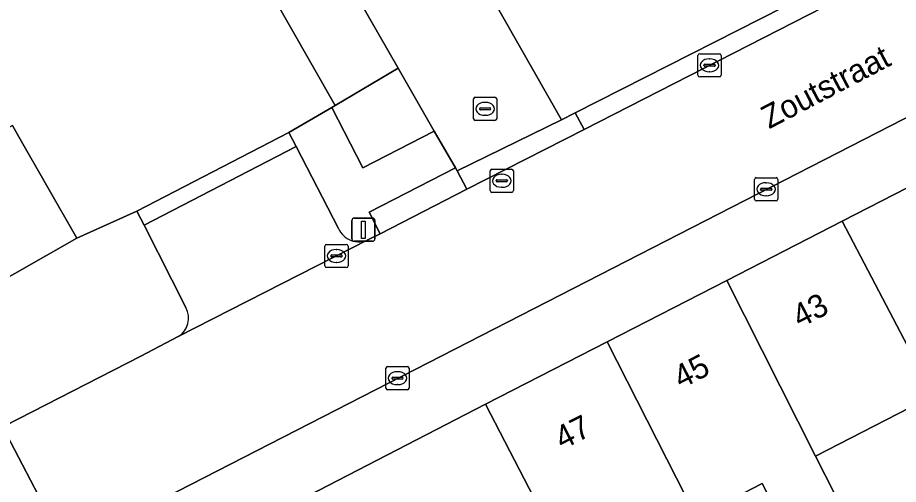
# Model space of a CAD drawing. Extents: x 159888 to 160761, y 384031 to 384750.
# Drawn here: x 160531.08 to 160569.11, y 384284.4 to 384304.54 of the extents above; entities that cross this region are included whole.
import ezdxf

# ---------------------------------------------------------------- set-up
doc = ezdxf.new("R2010")
doc.units = 0
for name, color, linetype in [('IMGEO_Erf', 7, 'Continuous'), ('IMGEO_Groenvoorziening', 7, 'Continuous'), ('IMGEO_Kolk', 7, 'Continuous'), ('IMGEO_Lichtmast', 7, 'Continuous'), ('IMGEO_Openbare_ruimte_label', 7, 'Continuous'), ('IMGEO_Pand', 7, 'Continuous'), ('IMGEO_Pand_nummerreeks', 7, 'Continuous'), ('IMGEO_Parkeervlak_open', 7, 'Continuous'), ('IMGEO_Rijbaan_lokaal_open', 7, 'Continuous'), ('IMGEO_Rioolput', 7, 'Continuous'), ('IMGEO_Voetpad_open', 7, 'Continuous')]:
    doc.layers.add(name, color=color, linetype=linetype)

msp = doc.modelspace()

# ---------------------------------------------------------------- linework, layer by layer
at = {"layer": 'IMGEO_Erf'}
for points in [[(160530.86, 384299.884), (160531.135, 384299.401), (160533.646, 384295.03), (160536.236, 384296.185), (160542.794, 384299.585), (160544.644, 384300.668), (160544.79, 384300.753), (160541.82, 384305.981), (160540.039, 384305.037), (160538.682, 384307.598), (160541.063, 384308.86), (160543.1, 384310.052), (160531.789, 384330.089), (160529.359, 384328.855)], [(160570.633, 384288.242), (160565.536, 384285.62), (160566.384, 384283.945), (160564.075, 384282.776), (160563.235, 384284.436), (160560.401, 384282.978), (160555.203, 384280.304), (160559.938, 384270.993), (160560.964, 384268.976), (160556.833, 384267.08), (160556.642, 384267.456), (160556.135, 384267.254), (160556.26, 384266.871), (160551.702, 384264.96), (160543.477, 384260.72), (160543.642, 384260.525), (160565.32, 384270.954), (160568.138, 384265.216), (160563.733, 384263.06), (160566.28, 384257.873)]]:
    msp.add_lwpolyline(points, dxfattribs=at)
at = {"layer": 'IMGEO_Groenvoorziening'}
msp.add_lwpolyline([(160558.102, 384270.191), (160559.938, 384270.993), (160555.203, 384280.304), (160553.584, 384283.42), (160551.279, 384287.856), (160533.88, 384278.879), (160536.442, 384278.002), (160537.944, 384277.697), (160549.322, 384283.817), (160551.212, 384280.795), (160550.654, 384280.266), (160550.225, 384279.629), (160550.169, 384278.862), (160550.319, 384278.053), (160551.037, 384276.806), (160552.885, 384276.185), (160550.436, 384268.6), (160548.359, 384269.253), (160543.871, 384263.833), (160544.188, 384263.332), (160544.342, 384263.416), (160550.681, 384266.684), (160553.787, 384268.003), (160553.651, 384268.417)], close=True, dxfattribs=at)
at = {"layer": 'IMGEO_Kolk'}
for p, q in [((160560.532, 384302.984), (160561.384, 384302.984)), ((160560.457, 384302.058), (160560.457, 384302.91)), ((160560.945, 384302.764), (160560.97, 384302.764)), ((160561.458, 384302.91), (160561.458, 384302.058)), ((160560.716, 384302.478), (160560.716, 384302.49)), ((160561.154, 384302.441), (160560.756, 384302.441)), ((160560.759, 384302.527), (160561.157, 384302.527)), ((160561.2, 384302.49), (160561.2, 384302.478)), ((160561.384, 384301.984), (160560.532, 384301.984)), ((160560.968, 384302.204), (160560.943, 384302.204)), ((160550.842, 384301.106), (160551.694, 384301.106)), ((160550.767, 384300.18), (160550.767, 384301.032)), ((160551.255, 384300.886), (160551.28, 384300.886)), ((160551.768, 384301.032), (160551.768, 384300.18)), ((160551.026, 384300.6), (160551.026, 384300.612)), ((160551.464, 384300.563), (160551.066, 384300.563)), ((160551.069, 384300.649), (160551.467, 384300.649)), ((160551.278, 384300.326), (160551.253, 384300.326)), ((160551.51, 384300.612), (160551.51, 384300.6)), ((160551.694, 384300.106), (160550.842, 384300.106)), ((160562.901, 384296.709), (160562.901, 384297.561)), ((160562.976, 384297.635), (160563.828, 384297.635)), ((160563.389, 384297.415), (160563.414, 384297.415)), ((160563.902, 384297.561), (160563.902, 384296.709)), ((160563.16, 384297.129), (160563.16, 384297.141)), ((160563.598, 384297.092), (160563.2, 384297.092)), ((160563.203, 384297.178), (160563.601, 384297.178)), ((160563.644, 384297.141), (160563.644, 384297.129)), ((160563.828, 384296.635), (160562.976, 384296.635)), ((160563.412, 384296.855), (160563.387, 384296.855)), ((160544.349, 384293.831), (160544.349, 384294.683)), ((160544.424, 384294.757), (160545.276, 384294.757)), ((160545.35, 384294.683), (160545.35, 384293.831)), ((160544.608, 384294.251), (160544.608, 384294.263)), ((160544.651, 384294.3), (160545.049, 384294.3)), ((160544.837, 384294.537), (160544.862, 384294.537)), ((160545.092, 384294.263), (160545.092, 384294.251)), ((160545.046, 384294.214), (160544.648, 384294.214)), ((160544.86, 384293.977), (160544.835, 384293.977)), ((160545.276, 384293.757), (160544.424, 384293.757)), ((160546.984, 384288.558), (160546.984, 384289.41)), ((160547.059, 384289.484), (160547.911, 384289.484)), ((160547.985, 384289.41), (160547.985, 384288.558)), ((160547.243, 384288.978), (160547.243, 384288.99)), ((160547.681, 384288.941), (160547.283, 384288.941)), ((160547.286, 384289.027), (160547.684, 384289.027)), ((160547.472, 384289.264), (160547.497, 384289.264)), ((160547.727, 384288.99), (160547.727, 384288.978)), ((160547.495, 384288.704), (160547.47, 384288.704)), ((160547.911, 384288.484), (160547.059, 384288.484))]:
    msp.add_line(p, q, dxfattribs=at)
for points in [[(160560.532, 384302.984), (160561.384, 384302.984)], [(160560.457, 384302.058), (160560.457, 384302.91)], [(160561.458, 384302.91), (160561.458, 384302.058)], [(160561.384, 384301.984), (160560.532, 384301.984)], [(160550.842, 384301.106), (160551.694, 384301.106)], [(160550.767, 384300.18), (160550.767, 384301.032)], [(160551.768, 384301.032), (160551.768, 384300.18)], [(160551.694, 384300.106), (160550.842, 384300.106)], [(160562.901, 384296.709), (160562.901, 384297.561)], [(160562.976, 384297.635), (160563.828, 384297.635)], [(160563.902, 384297.561), (160563.902, 384296.709)], [(160563.828, 384296.635), (160562.976, 384296.635)], [(160544.349, 384293.831), (160544.349, 384294.683)], [(160544.424, 384294.757), (160545.276, 384294.757)], [(160545.35, 384294.683), (160545.35, 384293.831)], [(160545.276, 384293.757), (160544.424, 384293.757)], [(160546.984, 384288.558), (160546.984, 384289.41)], [(160547.059, 384289.484), (160547.911, 384289.484)], [(160547.985, 384289.41), (160547.985, 384288.558)], [(160547.911, 384288.484), (160547.059, 384288.484)]]:
    msp.add_lwpolyline(points, dxfattribs=at)
for centre, radius, start, end in [((160560.534, 384302.908), 0.0765, 91.552, 178.448), ((160560.534, 384302.908), 0.0765, 91.552, 178.448), ((160561.382, 384302.908), 0.0765, 1.552, 88.448), ((160561.382, 384302.908), 0.0765, 1.552, 88.448), ((160560.756, 384302.487), 0.0403, 85.8775, 175.7526), ((160560.753, 384302.477), 0.0366, 178.938, 274.7102), ((160561.157, 384302.484), 0.043, 264.8664, 352.4533), ((160561.161, 384302.489), 0.0386, 1.7309, 96.639), ((160560.534, 384302.06), 0.0765, 181.552, 268.448), ((160560.534, 384302.06), 0.0765, 181.552, 268.448), ((160561.382, 384302.06), 0.0765, 271.552, 358.448), ((160561.382, 384302.06), 0.0765, 271.552, 358.448), ((160550.844, 384301.03), 0.0765, 91.552, 178.448), ((160550.844, 384301.03), 0.0765, 91.552, 178.448), ((160551.692, 384301.03), 0.0765, 1.552, 88.448), ((160551.692, 384301.03), 0.0765, 1.552, 88.448), ((160551.066, 384300.609), 0.0403, 85.8775, 175.7526), ((160551.063, 384300.599), 0.0366, 178.938, 274.7102), ((160551.467, 384300.606), 0.043, 264.8664, 352.4533), ((160551.471, 384300.611), 0.0386, 1.7309, 96.639), ((160550.844, 384300.182), 0.0765, 181.552, 268.448), ((160550.844, 384300.182), 0.0765, 181.552, 268.448), ((160551.692, 384300.182), 0.0765, 271.552, 358.448), ((160551.692, 384300.182), 0.0765, 271.552, 358.448), ((160562.978, 384297.559), 0.0765, 91.552, 178.448), ((160562.978, 384297.559), 0.0765, 91.552, 178.448), ((160563.826, 384297.559), 0.0765, 1.552, 88.448), ((160563.826, 384297.559), 0.0765, 1.552, 88.448), ((160563.2, 384297.138), 0.0403, 85.8775, 175.7526), ((160563.197, 384297.128), 0.0366, 178.938, 274.7102), ((160563.601, 384297.135), 0.043, 264.8664, 352.4533), ((160563.605, 384297.14), 0.0386, 1.7309, 96.639), ((160562.978, 384296.711), 0.0765, 181.552, 268.448), ((160562.978, 384296.711), 0.0765, 181.552, 268.448), ((160563.826, 384296.711), 0.0765, 271.552, 358.448), ((160563.826, 384296.711), 0.0765, 271.552, 358.448), ((160544.426, 384294.681), 0.0765, 91.552, 178.448), ((160544.426, 384294.681), 0.0765, 91.552, 178.448), ((160545.274, 384294.681), 0.0765, 1.552, 88.448), ((160545.274, 384294.681), 0.0765, 1.552, 88.448), ((160544.648, 384294.26), 0.0403, 85.8775, 175.7526), ((160544.645, 384294.25), 0.0366, 178.938, 274.7102), ((160545.049, 384294.257), 0.043, 264.8664, 352.4533), ((160545.053, 384294.262), 0.0386, 1.7309, 96.639), ((160544.426, 384293.833), 0.0765, 181.552, 268.448), ((160544.426, 384293.833), 0.0765, 181.552, 268.448), ((160545.274, 384293.833), 0.0765, 271.552, 358.448), ((160545.274, 384293.833), 0.0765, 271.552, 358.448), ((160547.061, 384289.408), 0.0765, 91.552, 178.448), ((160547.061, 384289.408), 0.0765, 91.552, 178.448), ((160547.909, 384289.408), 0.0765, 1.552, 88.448), ((160547.909, 384289.408), 0.0765, 1.552, 88.448), ((160547.283, 384288.987), 0.0403, 85.8775, 175.7526), ((160547.28, 384288.977), 0.0366, 178.938, 274.7102), ((160547.684, 384288.984), 0.043, 264.8664, 352.4533), ((160547.688, 384288.989), 0.0386, 1.7309, 96.639), ((160547.061, 384288.56), 0.0765, 181.552, 268.448), ((160547.061, 384288.56), 0.0765, 181.552, 268.448), ((160547.909, 384288.56), 0.0765, 271.552, 358.448), ((160547.909, 384288.56), 0.0765, 271.552, 358.448)]:
    msp.add_arc(centre, radius, start, end, dxfattribs=at)
for centre, major_axis, ratio, start_param, end_param in [((160560.944, 384302.484), (-0.387, 0.002), 0.722429, 4.712389, 7.853982), ((160560.969, 384302.484), (-0.39, 0.002), 0.717154, 1.570796, 4.712389), ((160551.254, 384300.606), (-0.387, 0.002), 0.722429, 4.712389, 7.853982), ((160551.279, 384300.606), (-0.39, 0.002), 0.717154, 1.570796, 4.712389), ((160563.388, 384297.135), (-0.387, 0.002), 0.722429, 4.712389, 7.853982), ((160563.413, 384297.135), (-0.39, 0.002), 0.717154, 1.570796, 4.712389), ((160544.836, 384294.257), (-0.387, 0.002), 0.722429, 4.712389, 7.853982), ((160544.861, 384294.257), (-0.39, 0.002), 0.717154, 1.570796, 4.712389), ((160547.471, 384288.984), (-0.387, 0.002), 0.722429, 4.712389, 7.853982), ((160547.496, 384288.984), (-0.39, 0.002), 0.717154, 1.570796, 4.712389)]:
    msp.add_ellipse(centre, major_axis=major_axis, ratio=ratio, start_param=start_param, end_param=end_param, dxfattribs=at)
at = {"layer": 'IMGEO_Lichtmast'}
for p, q in [((160545.518, 384294.989), (160545.518, 384295.789)), ((160545.518, 384295.789), (160545.518, 384294.989)), ((160545.618, 384295.889), (160546.408, 384295.889)), ((160546.408, 384295.889), (160545.618, 384295.889)), ((160546.508, 384295.789), (160546.508, 384294.989)), ((160546.508, 384294.989), (160546.508, 384295.789)), ((160546.408, 384294.889), (160545.618, 384294.889)), ((160545.618, 384294.889), (160546.408, 384294.889))]:
    msp.add_line(p, q, dxfattribs=at)
msp.add_lwpolyline([(160545.938, 384295.764), (160546.088, 384295.764), (160546.088, 384295.014), (160545.938, 384295.014), (160545.938, 384295.764)], dxfattribs=at)
for centre, start, end in [((160545.618, 384295.789), 90, 180), ((160545.618, 384295.789), 90, 180), ((160546.408, 384295.789), 0, 90), ((160546.408, 384295.789), 360, 90), ((160545.618, 384294.989), 180, 270), ((160545.618, 384294.989), 180, 270), ((160546.408, 384294.989), 270, 0), ((160546.408, 384294.989), 270, 0)]:
    msp.add_arc(centre, 0.1, start, end, dxfattribs=at)
at = {"layer": 'IMGEO_Pand'}
for points in [[(160548.767, 384340.417), (160543.753, 384337.869), (160535.033, 384333.437), (160543.096, 384320.156), (160543.393, 384320.307), (160546.274, 384314.638), (160552.084, 384304.47), (160554.565, 384300.129), (160555.152, 384300.427), (160566.162, 384306.023), (160566.326, 384306.106), (160564.1, 384310.488), (160558.407, 384321.685), (160555.55, 384327.303), (160553.091, 384332.138), (160548.858, 384340.463)], [(160544.563, 384307.504), (160542.425, 384306.371), (160541.82, 384305.981), (160544.79, 384300.753), (160547.519, 384302.353)], [(160531.135, 384299.401), (160530.86, 384299.884), (160522.681, 384295.336), (160525.5, 384290.386), (160533.646, 384295.03)], [(160575.718, 384290.858), (160571.766, 384298.366), (160566.688, 384295.761), (160570.633, 384288.242)], [(160570.633, 384288.242), (160566.688, 384295.761), (160561.699, 384293.201), (160565.536, 384285.62)], [(160561.699, 384293.201), (160556.531, 384290.55), (160560.401, 384282.978), (160563.235, 384284.436), (160564.075, 384282.776), (160566.384, 384283.945), (160565.536, 384285.62)], [(160560.401, 384282.978), (160556.531, 384290.55), (160551.279, 384287.856), (160553.584, 384283.42), (160555.203, 384280.304)]]:
    msp.add_lwpolyline(points, close=True, dxfattribs=at)
at = {"layer": 'IMGEO_Parkeervlak_open'}
for points in [[(160544.935, 384295.447), (160543.107, 384298.98), (160536.542, 384295.581), (160538.343, 384292.029)], [(160538.022, 384290.775), (160546.235, 384294.964)]]:
    msp.add_lwpolyline(points, dxfattribs=at)
for centre, radius, start, end in [((160545.819, 384295.835), 0.965, 203.6966, 295.5395), ((160537.541, 384291.566), 0.926, 301.3155, 29.9679)]:
    msp.add_arc(centre, radius, start, end, dxfattribs=at)
at = {"layer": 'IMGEO_Rijbaan_lokaal_open'}
msp.add_lwpolyline([(160543.1, 384310.052), (160544.563, 384307.504), (160547.519, 384302.353), (160549.071, 384299.635), (160549.994, 384298.058), (160550.066, 384297.935), (160554.565, 384300.129), (160552.084, 384304.47), (160546.274, 384314.638), (160543.393, 384320.307), (160543.096, 384320.156), (160535.033, 384333.437), (160531.14, 384331.368), (160531.789, 384330.089)], close=True, dxfattribs=at)
for points in [[(160612.124, 384331.359), (160596.143, 384321.577), (160595.889, 384321.422), (160590.108, 384317.85), (160586.028, 384315.337), (160572.443, 384308.324), (160567.462, 384305.807), (160566.53, 384305.339), (160555.538, 384299.708), (160550.478, 384297.137), (160546.731, 384295.217), (160546.235, 384294.964), (160538.022, 384290.775), (160536.409, 384289.932), (160530.529, 384286.928), (160530.447, 384286.864), (160533.164, 384281.656), (160533.808, 384281.997), (160534.575, 384282.359), (160579.578, 384305.42), (160588.356, 384309.89)], [(160532.184, 384281.146), (160533.164, 384281.656), (160530.447, 384286.864)]]:
    msp.add_lwpolyline(points, dxfattribs=at)
at = {"layer": 'IMGEO_Rioolput'}
for p, q in [((160551.486, 384297.076), (160551.486, 384297.928)), ((160551.561, 384298.002), (160552.413, 384298.002)), ((160551.974, 384297.782), (160551.999, 384297.782)), ((160552.487, 384297.928), (160552.487, 384297.076)), ((160551.745, 384297.496), (160551.745, 384297.508)), ((160552.183, 384297.459), (160551.785, 384297.459)), ((160551.788, 384297.545), (160552.186, 384297.545)), ((160552.229, 384297.508), (160552.229, 384297.496)), ((160552.413, 384297.002), (160551.561, 384297.002)), ((160551.997, 384297.222), (160551.972, 384297.222))]:
    msp.add_line(p, q, dxfattribs=at)
for points in [[(160551.486, 384297.076), (160551.486, 384297.928)], [(160551.561, 384298.002), (160552.413, 384298.002)], [(160552.487, 384297.928), (160552.487, 384297.076)], [(160552.413, 384297.002), (160551.561, 384297.002)]]:
    msp.add_lwpolyline(points, dxfattribs=at)
for centre, radius, start, end in [((160551.563, 384297.926), 0.0765, 91.552, 178.448), ((160551.563, 384297.926), 0.0765, 91.552, 178.448), ((160552.411, 384297.926), 0.0765, 1.552, 88.448), ((160552.411, 384297.926), 0.0765, 1.552, 88.448), ((160551.785, 384297.505), 0.0403, 85.8775, 175.7526), ((160551.782, 384297.495), 0.0366, 178.938, 274.7102), ((160552.186, 384297.502), 0.043, 264.8664, 352.4533), ((160552.19, 384297.507), 0.0386, 1.7309, 96.639), ((160551.563, 384297.078), 0.0765, 181.552, 268.448), ((160551.563, 384297.078), 0.0765, 181.552, 268.448), ((160552.411, 384297.078), 0.0765, 271.552, 358.448), ((160552.411, 384297.078), 0.0765, 271.552, 358.448)]:
    msp.add_arc(centre, radius, start, end, dxfattribs=at)
for centre, major_axis, ratio, start_param, end_param in [((160551.973, 384297.502), (-0.387, 0.002), 0.722429, 4.712389, 7.853982), ((160551.998, 384297.502), (-0.39, 0.002), 0.717154, 1.570796, 4.712389)]:
    msp.add_ellipse(centre, major_axis=major_axis, ratio=ratio, start_param=start_param, end_param=end_param, dxfattribs=at)
at = {"layer": 'IMGEO_Voetpad_open'}
for points in [[(160538.343, 384292.029), (160536.542, 384295.581), (160536.236, 384296.185), (160533.646, 384295.03), (160525.5, 384290.386), (160522.681, 384295.336), (160519.831, 384300.342), (160517.105, 384305.128), (160516.833, 384305.606), (160515.819, 384305.009), (160515.66, 384305.306), (160512.421, 384311.338), (160509.525, 384316.732), (160509.071, 384317.578), (160509.76, 384317.924), (160509.399, 384318.55), (160506.895, 384322.893), (160504.433, 384327.161), (160504.362, 384327.285), (160500.86, 384333.269)], [(160616.128, 384326.145), (160615.782, 384325.978), (160607.558, 384321.885), (160588.848, 384310.16), (160588.356, 384309.89), (160588.842, 384308.937), (160580.064, 384304.467), (160579.578, 384305.42), (160534.575, 384282.359), (160533.808, 384281.997), (160533.164, 384281.656), (160532.184, 384281.146)], [(160531.518, 384280.714), (160533.414, 384277.545), (160533.88, 384278.879), (160551.279, 384287.856), (160556.531, 384290.55), (160561.699, 384293.201), (160566.688, 384295.761), (160571.766, 384298.366), (160576.844, 384300.971), (160582.038, 384303.635)], [(160546.235, 384294.964), (160546.731, 384295.217), (160546.257, 384296.143), (160549.994, 384298.058), (160549.071, 384299.635), (160545.992, 384298.061), (160544.644, 384300.668), (160542.794, 384299.585), (160543.107, 384298.98), (160544.935, 384295.447)], [(160529.391, 384286.344), (160530.447, 384286.864), (160530.529, 384286.928), (160536.409, 384289.932), (160538.022, 384290.775)]]:
    msp.add_lwpolyline(points, dxfattribs=at)
for points in [[(160555.538, 384299.708), (160566.53, 384305.339), (160566.162, 384306.023), (160555.152, 384300.427)], [(160549.071, 384299.635), (160547.519, 384302.353), (160544.79, 384300.753), (160544.644, 384300.668), (160545.992, 384298.061)], [(160550.478, 384297.137), (160555.538, 384299.708), (160555.152, 384300.427), (160554.565, 384300.129), (160550.066, 384297.935)], [(160543.107, 384298.98), (160542.794, 384299.585), (160536.236, 384296.185), (160536.542, 384295.581)], [(160546.257, 384296.143), (160546.731, 384295.217), (160550.478, 384297.137), (160550.066, 384297.935), (160549.994, 384298.058)]]:
    msp.add_lwpolyline(points, close=True, dxfattribs=at)
for centre, radius, start, end in [((160545.819, 384295.835), 0.965, 203.6966, 295.5395), ((160537.541, 384291.566), 0.926, 301.3155, 29.9679)]:
    msp.add_arc(centre, radius, start, end, dxfattribs=at)

# ---------------------------------------------------------------- texts
at = {"layer": 'IMGEO_Openbare_ruimte_label'}
msp.add_text('Zoutstraat', height=1, rotation=27.6411, dxfattribs=at).set_placement((160563.526, 384299.718))
at = {"layer": 'IMGEO_Pand_nummerreeks'}
for s, rotation, p in [('43', 27.1573, (160564.857, 384291.135)), ('45', 27.1582, (160559.73, 384288.505)), ('47', 27.1573, (160554.604, 384285.876))]:
    msp.add_text(s, height=1, rotation=rotation, dxfattribs=at).set_placement(p)

doc.saveas('drawing.dxf')
